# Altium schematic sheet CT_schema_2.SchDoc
size 276 x 169 mm
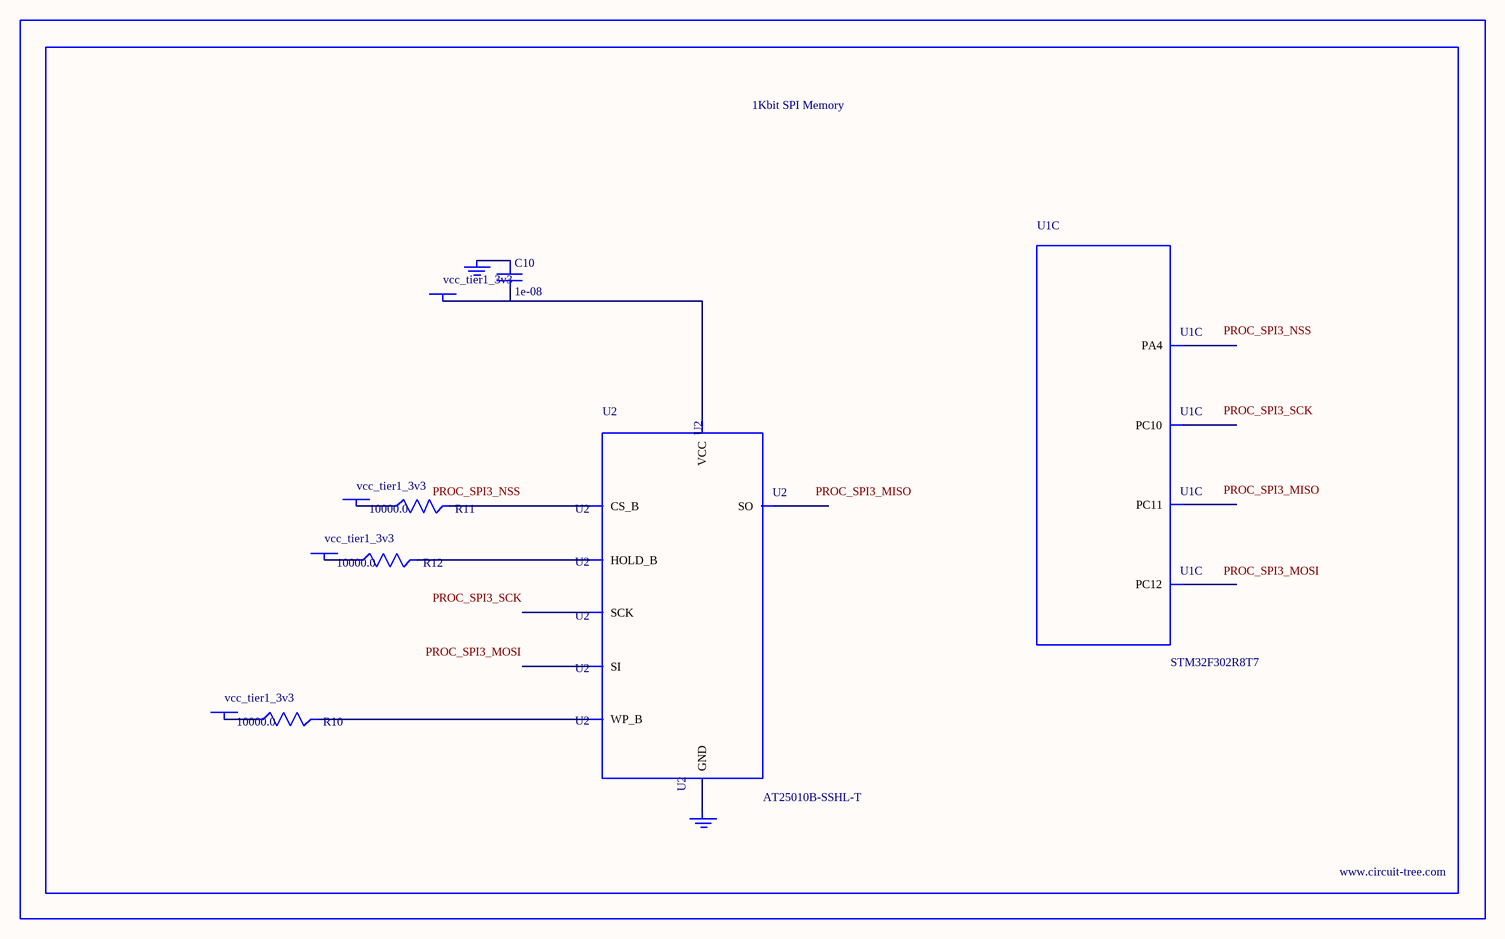
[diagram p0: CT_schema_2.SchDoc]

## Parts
BORDER1  (no value)
C10  1e-08  [C0402]
GND_INSTANCE_1_0  (no value)
GND_INSTANCE_1_1  (no value)
POWER_INSTANCE_1_0  vcc_tier1_3v3
POWER_INSTANCE_1_1  vcc_tier1_3v3
POWER_INSTANCE_1_2  vcc_tier1_3v3
POWER_INSTANCE_1_3  vcc_tier1_3v3
R10  10000.0  [R0603]
R11  10000.0  [R0603]
R12  10000.0  [R0603]
U1  STM32F302R8T7  [LQFP64]  (part C of 8)
U2  AT25010B-SSHL-T  [SOIC-8]

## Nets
NetC10_1: C10.1 GND_INSTANCE_1_0.0(GND)
NetC10_2: C10.2 POWER_INSTANCE_1_3.0(PWR) U2.8(VCC)
NetGND_INSTANCE_1_1_0: GND_INSTANCE_1_1.0(GND) U2.4(GND)
NetPOWER_INSTANCE_1_0_0: POWER_INSTANCE_1_0.0(PWR) R11.1
NetPOWER_INSTANCE_1_1_0: POWER_INSTANCE_1_1.0(PWR) R10.1
NetPOWER_INSTANCE_1_2_0: POWER_INSTANCE_1_2.0(PWR) R12.1
NetR10_2: R10.2 U2.3(WP_B)
NetR11_2: R11.2 U2.1(CS_B)
NetR12_2: R12.2 U2.7(HOLD_B)

Not connected (* = marked no-connect by the designer): U1 20(PA4) 51(PC10) 52(PC11) 53(PC12); U2 2(SO) 5(SI) 6(SCK)

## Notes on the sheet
- Labels drawn without touching a wire or pin: PROC_SPI3_MISO, PROC_SPI3_MOSI, PROC_SPI3_NSS, PROC_SPI3_SCK

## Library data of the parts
BORDER1 = BORDER_PAGE1
C10 = C0402C103K3RAC
GND_INSTANCE_1_0 GND_INSTANCE_1_1 = GND
POWER_INSTANCE_1_0-POWER_INSTANCE_1_3 = PWR
R10-R12 = RC0603JR-0710KL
